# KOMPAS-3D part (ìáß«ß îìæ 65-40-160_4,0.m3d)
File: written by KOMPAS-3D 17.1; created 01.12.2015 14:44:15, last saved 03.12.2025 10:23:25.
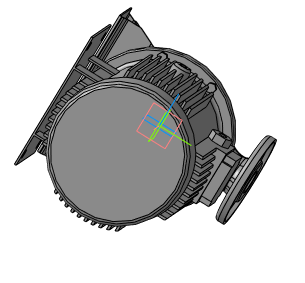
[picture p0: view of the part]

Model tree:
1. Операция без истории:5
